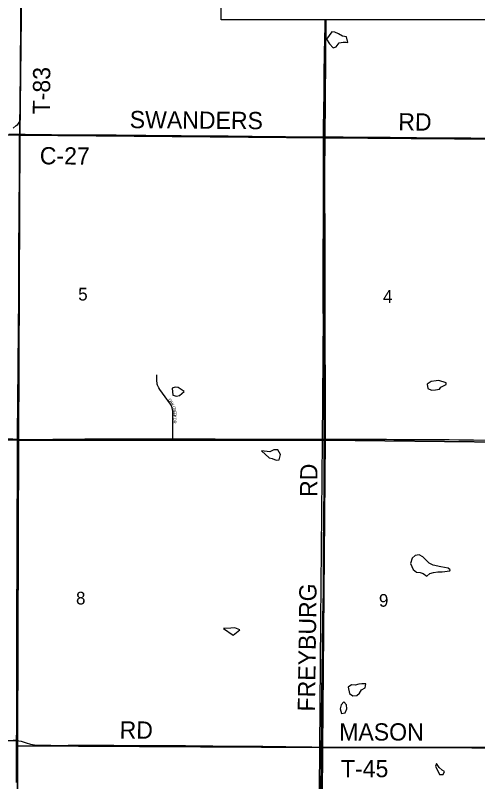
# Model space of a CAD drawing. Extents: x -784 to 1375, y -225 to 440.
# Drawn here: x 519.3 to 549.7, y 311.4 to 362 of the extents above; entities that cross this region are included whole.
import ezdxf

# ---------------------------------------------------------------- set-up
doc = ezdxf.new("R2010")
doc.units = 0
for name, color, linetype in [('GM_X_County_Road', 7, 'Continuous'), ('GM_X_County_Road_Text', 7, 'Continuous'), ('GM_X_Minor_Lake', 7, 'Continuous'), ('GM_X_Section', 7, 'Continuous'), ('GM_X_Section_Text', 7, 'Continuous'), ('GM_X_Township', 7, 'Continuous'), ('GM_X_Township_Road', 7, 'Continuous'), ('GM_X_Township_Road_Text', 7, 'Continuous'), ('GM_X_Township_Subdivision', 7, 'Continuous'), ('GM_X_Township_Subdivision_Text', 7, 'Continuous'), ('SH_Text', 7, 'Continuous')]:
    doc.layers.add(name, color=color, linetype=linetype)

msp = doc.modelspace()

# ---------------------------------------------------------------- linework, layer by layer
at = {"layer": 'GM_X_County_Road'}
for points in [[(539.584, 353.948), (539.593, 354.499), (539.608, 355.767), (539.616, 356.761), (539.632, 358.066), (539.659, 359.519), (539.683, 361.259), (539.689, 361.675)], [(518.843, 354.126), (518.952, 354.125), (519.511, 354.121), (519.555, 354.12)], [(519.555, 354.12), (519.909, 354.117), (520.058, 354.116), (520.369, 354.111), (520.89, 354.104), (521.648, 354.097), (522.444, 354.094), (523.053, 354.089), (523.686, 354.09), (524.246, 354.088), (525.501, 354.078), (525.911, 354.074), (526.321, 354.072), (526.644, 354.071), (527.017, 354.063), (527.862, 354.054), (528.433, 354.048), (529.042, 354.044), (529.44, 354.041), (529.701, 354.04), (530.211, 354.03), (530.571, 354.024), (531.267, 354.02), (532.149, 354.019), (533.305, 354.009), (533.976, 354.004), (534.398, 353.999), (534.883, 353.996), (535.952, 353.983), (537.07, 353.972), (538.002, 353.962), (538.785, 353.956), (539.456, 353.949), (539.584, 353.948)], [(539.625, 334.027), (539.625, 334.143), (539.609, 337.486), (539.6, 338.828), (539.593, 339.847), (539.584, 341.363), (539.568, 343.228), (539.565, 344.818), (539.563, 345.44), (539.57, 346.583), (539.572, 347.888), (539.575, 349.752), (539.577, 351.231), (539.572, 352.014), (539.572, 352.449), (539.573, 352.897), (539.58, 353.741), (539.584, 353.948)], [(539.584, 353.948), (540.879, 353.942), (541.737, 353.937), (542.843, 353.924), (543.986, 353.919), (545.713, 353.908), (547.453, 353.895), (548.049, 353.891), (549.292, 353.884), (550.795, 353.866), (551.491, 353.86), (552.249, 353.851), (553.057, 353.845), (553.526, 353.843)], [(539.591, 327.568), (539.594, 328.203), (539.602, 328.998), (539.618, 330.825), (539.625, 331.956), (539.627, 333.435), (539.625, 334.027)], [(539.548, 322.168), (539.565, 323.221), (539.573, 323.83), (539.586, 325.234), (539.586, 325.657), (539.589, 326.985), (539.591, 327.568)], [(539.431, 313.71), (539.447, 314.638), (539.459, 316.041), (539.48, 317.258), (539.494, 318.65), (539.525, 320.401), (539.545, 322.016), (539.548, 322.168)], [(519.122, 314.174), (519.27, 314.165), (519.354, 314.155)], [(519.354, 314.155), (519.38, 314.153), (519.5, 314.13), (519.644, 314.094), (519.976, 313.993), (520.276, 313.907), (520.398, 313.88), (520.534, 313.859), (520.684, 313.845), (520.896, 313.835), (521.231, 313.829), (521.617, 313.829), (522.176, 313.827), (522.76, 313.831), (523.394, 313.831), (524.239, 313.829), (525.195, 313.83), (525.767, 313.83), (526.934, 313.824), (527.357, 313.823), (527.705, 313.823), (528.264, 313.82), (528.91, 313.818), (530.476, 313.806), (531.308, 313.8), (531.581, 313.798), (532.277, 313.792), (533.37, 313.783), (533.88, 313.778), (534.265, 313.773), (534.551, 313.771), (535.22, 313.766), (535.581, 313.763), (536.276, 313.752), (537.096, 313.74), (537.954, 313.727), (538.451, 313.723), (538.823, 313.723), (539.27, 313.714), (539.431, 313.71)], [(539.39, 309.166), (539.396, 309.968), (539.412, 311.322), (539.418, 312.316), (539.423, 313.272), (539.425, 313.37)], [(539.425, 313.37), (539.431, 313.71)]]:
    msp.add_lwpolyline(points, dxfattribs=at)
at = {"layer": 'GM_X_Minor_Lake'}
for p, q in [((546.416, 337.637), (546.457, 337.348)), ((529.611, 337.378), (529.648, 336.923)), ((541.211, 317.661), (541.303, 317.25)), ((542.098, 317.491), (542.336, 317.63)), ((547.028, 312.622), (546.955, 312.464))]:
    msp.add_line(p, q, dxfattribs=at)
for points in [[(541.184, 360.168), (541.092, 360.544), (540.827, 360.588), (540.571, 360.752), (540.322, 360.848), (540.133, 360.875), (539.787, 360.396)], [(539.787, 360.396), (539.989, 360.075), (540.22, 359.813), (540.412, 359.892), (540.614, 360.153), (540.873, 360.201), (541.063, 360.189), (541.184, 360.168)], [(547.011, 337.869), (546.678, 337.821), (546.416, 337.637)], [(546.965, 337.262), (547.225, 337.324), (547.327, 337.443), (547.659, 337.625), (547.677, 337.738), (547.194, 337.888), (547.011, 337.869)], [(530.402, 337.166), (529.999, 337.415), (529.81, 337.449), (529.611, 337.378)], [(529.648, 336.923), (529.898, 336.857), (530.089, 336.906), (530.402, 337.166)], [(546.457, 337.348), (546.698, 337.252), (546.965, 337.262)], [(536.746, 333.001), (536.57, 333.308), (536.304, 333.306), (536.036, 333.191), (535.499, 333.248)], [(535.499, 333.248), (535.991, 332.775), (536.188, 332.741), (536.459, 332.629), (536.658, 332.655), (536.746, 333.001)], [(546.804, 325.701), (546.548, 325.835), (546.354, 326.043), (546.122, 326.253), (545.881, 326.379), (545.63, 326.339), (545.429, 326.176), (545.31, 325.807)], [(545.31, 325.807), (545.492, 325.418), (545.702, 325.247), (545.952, 325.234), (546.149, 325.162), (546.396, 324.99), (546.597, 325.152), (546.826, 325.223)], [(546.826, 325.223), (547.116, 325.261), (547.406, 325.277), (547.909, 325.325), (547.934, 325.408), (547.808, 325.518), (547.308, 325.599), (546.804, 325.701)], [(534.064, 321.448), (533.732, 321.583), (533.48, 321.551), (532.985, 321.522)], [(532.985, 321.522), (533.632, 321.101), (534.064, 321.448)], [(542.336, 317.63), (542.363, 317.872), (542.104, 317.877), (541.914, 317.851), (541.662, 317.788), (541.434, 317.816), (541.211, 317.661)], [(541.303, 317.25), (541.521, 317.102), (541.772, 317.112), (541.964, 317.259), (542.098, 317.491)], [(541.13, 316.239), (541.092, 316.505), (540.921, 316.698), (540.75, 316.504), (540.68, 316.229)], [(540.68, 316.229), (540.763, 315.928), (541.014, 315.969), (541.13, 316.239)], [(546.955, 312.464), (547.222, 311.902), (547.481, 311.91), (547.56, 312.104)], [(547.56, 312.104), (547.412, 312.194), (547.204, 312.359), (547.028, 312.622)]]:
    msp.add_lwpolyline(points, dxfattribs=at)
at = {"layer": 'GM_X_Section'}
for points in [[(539.743, 361.675), (539.64, 353.876), (519.562, 354.071), (519.776, 373.558), (524.658, 374.163), (539.907, 374.093), (539.903, 373.821)], [(559.674, 361.675), (559.644, 353.735), (539.64, 353.876), (539.743, 361.675)]]:
    msp.add_lwpolyline(points, dxfattribs=at)
for points in [[(506.617, 371.896), (519.776, 373.558), (519.562, 354.071), (499.42, 354.13), (499.684, 371.026)], [(519.562, 354.071), (519.48, 333.952), (499.931, 334.47), (499.944, 344.47), (499.42, 354.13)], [(519.562, 354.071), (539.64, 353.876), (539.683, 333.96), (519.48, 333.952)], [(559.644, 353.735), (559.365, 333.735), (539.683, 333.96), (539.64, 353.876)], [(519.48, 333.952), (519.411, 314.122), (499.543, 314.191), (499.901, 324.411), (499.931, 334.47)], [(519.48, 333.952), (539.683, 333.96), (539.515, 313.692), (519.42, 313.796), (519.411, 314.122)], [(539.683, 333.96), (559.365, 333.735), (559.175, 313.642), (539.515, 313.692)], [(519.411, 314.122), (519.42, 313.796), (519.407, 293.691), (499.2, 293.85), (499.543, 314.191)], [(519.42, 313.796), (539.515, 313.692), (539.382, 293.628), (519.407, 293.691)], [(539.515, 313.692), (559.175, 313.642), (559.1, 293.569), (539.382, 293.628)]]:
    msp.add_lwpolyline(points, close=True, dxfattribs=at)
at = {"layer": 'GM_X_Township'}
for points in [[(539.731, 361.675), (539.664, 353.833), (539.563, 342.208), (539.492, 333.882), (539.39, 322.02), (539.32, 313.642), (539.251, 305.289), (539.16, 293.586), (533.956, 293.601), (527.265, 293.606), (519.34, 293.604), (517.829, 293.627)], [(539.731, 361.675), (539.664, 353.833), (539.563, 342.208), (539.492, 333.882), (539.39, 322.02), (539.32, 313.642), (539.251, 305.289)]]:
    msp.add_lwpolyline(points, dxfattribs=at)
at = {"layer": 'GM_X_Township_Road'}
for points in [[(519.122, 354.516), (519.334, 354.691), (519.428, 354.775), (519.479, 354.833), (519.514, 354.888), (519.54, 354.947), (519.558, 355.008), (519.57, 355.084), (519.577, 355.21), (519.585, 355.683), (519.589, 356.378), (519.594, 356.962), (519.602, 357.596), (519.606, 358.243), (519.614, 359.461), (519.623, 360.529), (519.63, 361.399), (519.633, 361.797), (519.642, 362.729)], [(519.417, 334.015), (519.418, 334.117), (519.417, 334.229), (519.419, 334.589), (519.42, 334.912), (519.421, 335.073), (519.428, 335.756), (519.432, 336.129), (519.435, 336.701), (519.44, 337.21), (519.446, 338.067), (519.449, 338.788), (519.46, 339.707), (519.468, 340.341), (519.473, 340.726), (519.485, 341.497), (519.489, 341.907), (519.493, 342.677), (519.498, 343.609), (519.5, 343.895), (519.5, 344.367), (519.503, 344.852), (519.503, 345.597), (519.504, 346.306), (519.508, 346.778), (519.51, 347.138), (519.518, 348.157), (519.52, 348.903), (519.523, 349.3), (519.528, 349.897), (519.536, 350.742), (519.541, 351.314), (519.544, 351.935), (519.547, 352.295), (519.552, 352.941), (519.552, 353.364), (519.555, 353.799), (519.555, 353.936), (519.555, 353.996), (519.555, 354.12)], [(513.851, 334.32), (513.919, 334.317), (514.205, 334.302), (514.614, 334.286), (515.049, 334.264), (515.334, 334.245), (515.756, 334.221), (516.761, 334.164), (517.22, 334.14), (517.48, 334.124), (517.828, 334.105), (518.125, 334.087), (518.361, 334.07), (518.671, 334.054), (519.105, 334.03), (519.417, 334.015)], [(519.417, 334.015), (519.465, 334.012), (519.875, 334.004), (520.919, 334), (521.156, 334.001), (521.74, 334.012), (522.05, 334.017), (522.51, 334.02), (522.783, 334.022), (523.342, 334.027), (523.852, 334.029), (524.411, 334.03), (524.796, 334.03), (525.417, 334.035), (526.051, 334.035), (526.685, 334.037), (527.207, 334.038), (527.778, 334.042), (528.039, 334.042), (528.598, 334.039), (529.12, 334.043), (529.381, 334.045), (529.643, 334.046)], [(529.643, 334.046), (530.275, 334.048), (530.709, 334.046), (531.157, 334.037), (531.592, 334.035), (532.052, 334.034), (532.437, 334.032), (532.871, 334.024), (533.754, 334.022), (534.164, 334.022), (534.922, 334.02), (535.78, 334.021), (536.91, 334.017), (537.718, 334.019), (538.439, 334.023), (539.148, 334.023), (539.625, 334.027)], [(539.625, 334.027), (539.657, 334.027), (539.93, 334.023), (540.241, 334.019), (540.663, 334.019), (541.11, 334.016), (541.831, 334.014), (542.291, 334.013), (542.8, 334.008), (543.745, 334.007), (544.217, 334.004), (544.987, 333.999), (545.67, 333.995), (545.993, 333.992), (546.514, 333.986), (546.837, 333.987), (547.496, 333.988), (547.856, 333.986), (548.502, 333.982), (548.713, 333.978), (549.471, 333.967), (550.241, 333.952)], [(519.354, 314.155), (519.356, 314.224), (519.363, 314.808), (519.363, 315.143), (519.365, 315.653), (519.364, 316.15), (519.367, 316.672), (519.368, 317.156), (519.373, 318.088), (519.374, 318.424), (519.376, 319.319), (519.378, 320.213), (519.377, 320.71), (519.376, 321.282), (519.375, 321.48), (519.378, 322.412), (519.377, 322.984), (519.377, 323.556), (519.379, 323.941), (519.382, 324.338), (519.386, 324.997), (519.391, 325.73), (519.392, 326.003), (519.391, 326.438), (519.392, 326.885), (519.393, 327.407), (519.395, 327.904), (519.396, 328.252), (519.394, 328.873), (519.397, 329.817), (519.404, 330.389), (519.403, 331.035), (519.41, 331.768), (519.413, 332.141), (519.412, 332.439), (519.415, 332.762), (519.416, 333.172), (519.417, 333.694), (519.417, 333.967), (519.417, 334.015)], [(519.345, 311.367), (519.344, 311.615), (519.343, 312.075), (519.344, 312.808), (519.351, 313.814), (519.354, 314.155)], [(539.431, 313.71), (539.717, 313.707), (540.093, 313.703), (541.777, 313.711), (542.447, 313.71), (543.18, 313.712), (544.41, 313.712), (545.031, 313.71), (545.64, 313.711), (546.299, 313.712), (547.492, 313.711), (547.777, 313.71), (548.709, 313.702), (549.243, 313.703), (550.262, 313.697), (551.045, 313.694), (552.212, 313.692), (553.206, 313.689), (553.802, 313.68), (554.259, 313.673)]]:
    msp.add_lwpolyline(points, dxfattribs=at)
at = {"layer": 'GM_X_Township_Subdivision'}
msp.add_lwpolyline([(529.643, 334.046), (529.644, 334.193), (529.65, 335.261), (529.649, 335.719), (529.643, 335.867), (529.629, 335.976), (529.609, 336.058), (529.577, 336.15), (529.555, 336.202), (529.531, 336.251), (529.491, 336.326), (529.43, 336.418), (529.153, 336.799), (528.96, 337.058), (528.795, 337.292), (528.728, 337.398), (528.682, 337.488), (528.648, 337.57), (528.627, 337.643), (528.609, 337.73), (528.599, 337.83), (528.597, 337.968), (528.601, 338.266)], dxfattribs=at)
at = {"layer": 'SH_Text'}
msp.add_lwpolyline([(532.832, 373.821), (579.839, 373.821), (579.839, 361.675), (532.832, 361.675)], close=True, dxfattribs=at)

# ---------------------------------------------------------------- texts
at = {"layer": 'GM_X_County_Road_Text'}
for s, rotation, p in [('SWANDERS', 359.5037, (526.806, 354.528)), ('RD', 359.5056, (544.508, 354.378)), ('C-27', 359.6567, (520.88, 352.14)), ('RD', 89.5171, (539.169, 330.202)), ('FREYBURG', 89.2464, (539.019, 316.054)), ('RD', 359.5169, (526.139, 314.278))]:
    msp.add_text(s, height=1.1364, rotation=rotation, dxfattribs=at).set_placement(p)
at = {"layer": 'GM_X_Section_Text'}
for s, p in [('5', (523.411, 343.16)), ('4', (543.503, 343.005)), ('8', (523.27, 323.116)), ('9', (543.236, 322.966))]:
    msp.add_text(s, height=0.837, rotation=0, dxfattribs=at).set_placement(p)
at = {"layer": 'GM_X_Township_Road_Text'}
for s, rotation, p in [('T-83', 89.6458, (521.556, 355.429)), ('MASON', 0, (540.617, 314.145)), ('T-45', 0, (540.733, 311.726))]:
    msp.add_text(s, height=1.1364, rotation=rotation, dxfattribs=at).set_placement(p)
at = {"layer": 'GM_X_Township_Subdivision_Text'}
for s, rotation, p in [('O', 303.5022, (529.33, 336.618)), ('A', 303.5209, (529.422, 336.479)), ('K', 300.6939, (529.512, 336.342)), ('C', 288.819, (529.614, 336.163)), ('R', 278.2125, (529.66, 336.03)), ('E', 271.8036, (529.681, 335.887)), ('E', 270.2459, (529.685, 335.755)), ('K', 270, (529.686, 335.622)), ('D', 269.9928, (529.686, 335.405)), ('R', 269.994, (529.686, 335.238))]:
    msp.add_text(s, height=0.189, rotation=rotation, dxfattribs=at).set_placement(p)

doc.saveas('drawing.dxf')
